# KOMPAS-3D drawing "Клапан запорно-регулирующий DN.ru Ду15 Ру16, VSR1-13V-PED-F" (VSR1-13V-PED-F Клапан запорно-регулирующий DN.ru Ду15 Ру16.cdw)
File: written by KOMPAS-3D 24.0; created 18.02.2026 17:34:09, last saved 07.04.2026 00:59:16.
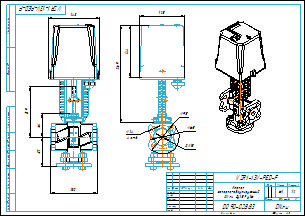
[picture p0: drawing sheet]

Document properties: Автор: R2D2; Форматы листов документа: A3; Полное имя файла: VSR1-13V-PED-F Клапан запорно-регулирующий DN.ru Ду15 Ру16.m3d; Масса: 6.1; Наименование: Клапан запорно-регулирующий DN.ru Ду15 Ру16; Количество листов документа: 1; Примечание: D090-02883

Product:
- Part/product: Клапан запорно-регулирующий DN.ru Ду15 Ру16  | designation VSR1-13V-PED-F
    Масса: 6.1
    Раздел спецификации: Прочие изделия
    Форматы листов документа: A3
    Примечание: D090-02883

Views: Вид 1, Спереди
Referenced files in E:\Работа\Зайцев\Солянка\VSR1-13V-PED-F Клапан запорно-регулирующий DN.ru\DN15\DN15 Kv0.16\: VSR1-13V-PED-F Клапан запорно-регулирующий DN.ru Ду15 Ру16.m3d
Referenced files in E:\Работа\Зайцев\Для компаса\: чертеж DN.ru А3.cdt
Referenced files in E:\Работа\Зайцев\Солянка\VSR1-13V-PED-F Клапан запорно-регулирующий DN.ru\DN15\DN15 Kv0.8\: VSR1-13V-PED-F Клапан запорно-регулирующий DN.ru Ду15 Ру16.m3d
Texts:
  Линейный размер
  VSR1-13V-PED-F
  чертеж DN.ru А3.cdt
  Клапан
  запорно-регулирующий
  DN.ru Ду15 Ру16
  Клапан запорно-регулирующий DN.ru Ду15 Ру16
  VSR1-13V-PED-F Клапан запорно-регулирующий DN.ru Ду15 Ру16
Dimensions and other numbers on the sheet: 0; 3; 2; 4; 130; 82; 143; 64; 139; 1:2; 1; 6,1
